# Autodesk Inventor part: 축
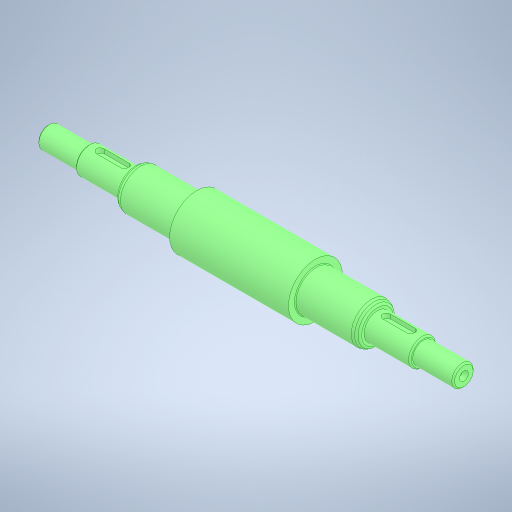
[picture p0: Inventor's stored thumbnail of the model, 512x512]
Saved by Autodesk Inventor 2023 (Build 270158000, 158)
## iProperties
Created: 2025-10
Part Number: 축
Material: 강철, 탄소
Document SubType Name: Modeling
Designer: home
Density: 7.85 g/cm^3
Appearance: 기본값
Author: jhkim
Sending System: Autodesk Inventor 2026
Preprocessor: ST-DEVELOPER v20.1
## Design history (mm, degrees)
sketch "스케치1"
  geometry: 1 further point
  constraints: 1 other
feature "솔리드1"
node "솔리드2"
